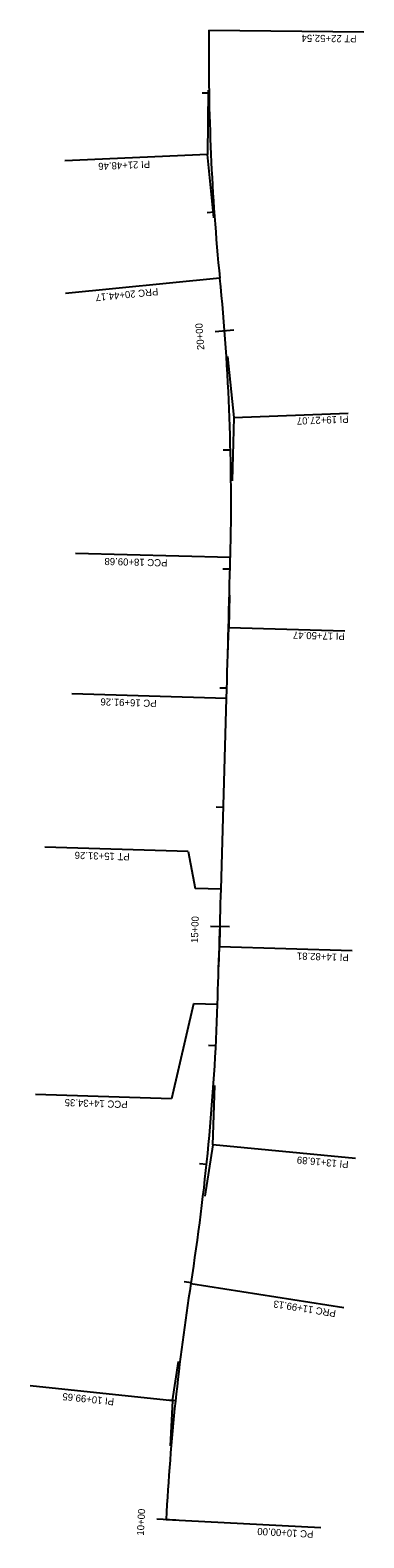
# Model space of a CAD drawing. Extents: x 1445613 to 1446340, y 2043492 to 2056486.
# Drawn here: x 1445971 to 1446251, y 2043492 to 2044757 of the extents above; entities that cross this region are included whole.
import ezdxf

# ---------------------------------------------------------------- set-up
doc = ezdxf.new("R2010")
doc.units = 0
for name, color, linetype in [('R_Horz Alg', 7, 'Continuous'), ('R_Horz Alg Annot', 7, 'Continuous'), ('R_Horz Alg Stationing', 7, 'Continuous')]:
    doc.layers.add(name, color=color, linetype=linetype)

msp = doc.modelspace()

# ---------------------------------------------------------------- linework, layer by layer
at = {"layer": 'R_Horz Alg'}
msp.add_line((1446131, 2044036.1), (1446135.6, 2044196.1), dxfattribs=at)
for centre, radius, start, end in [((1448030.5, 2044737.1), 1909.9, 179.4129, 185.664), ((1444229.5, 2044360.1), 1909.9, 358.629, 5.664), ((1423202.5, 2044863.3), 22942.8, 358.33333, 358.62905), ((1423197.9, 2044703.4), 22942.8, 358.09132, 358.33333), ((1444219.2, 2044002.9), 1909.9, 351.0345, 358.0913), ((1447992.2, 2043407.6), 1909.9, 171.0345, 177.0083)]:
    msp.add_arc(centre, radius, start, end, dxfattribs=at)
at = {"layer": 'R_Horz Alg Annot'}
for p, q in [((1446120.3, 2044706.3), (1446119.7, 2044652.4)), ((1446125, 2044599.2), (1446119.7, 2044652.4)), ((1446136.5, 2044482.8), (1446141.6, 2044431.8)), ((1446141.6, 2044431.8), (1446140.3, 2044378.7)), ((1446141.6, 2044431.8), (1446237.7, 2044435.4)), ((1446138, 2044282.6), (1446137.4, 2044255.2)), ((1446136.8, 2044234.2), (1446137.4, 2044255.2)), ((1446234.8, 2044252.6), (1446137.4, 2044255.2)), ((1446103.5, 2044067.7), (1446109.3, 2044036.7)), ((1446130, 2044003.5), (1446129.6, 2043987.7)), ((1446129, 2043970.8), (1446129.6, 2043987.7)), ((1446240.9, 2043984.2), (1446129.6, 2043987.7)), ((1446107.9, 2043939.9), (1446089.3, 2043860.1)), ((1446124, 2043821.6), (1446125.7, 2043871.3)), ((1446124, 2043821.6), (1446117.3, 2043778.6)), ((1446243.8, 2043810.2), (1446124, 2043821.6)), ((1446090.2, 2043606.8), (1446095.4, 2043639.7)), ((1446090.2, 2043606.8), (1446088.2, 2043569))]:
    msp.add_line(p, q, dxfattribs=at)
for points in [[(1446120.8, 2044756.7), (1446250.8, 2044755.3)], [(1446119.7, 2044652.4), (1445999.8, 2044647.1)], [(1446130, 2044548.6), (1446000.6, 2044535.8)], [(1446138.8, 2044314.4), (1446008.8, 2044317.5)], [(1446135.6, 2044196.1), (1446005.7, 2044199.8)], [(1446103.5, 2044067.7), (1445983.1, 2044071.2)], [(1446131, 2044036.1), (1446109.3, 2044036.7)], [(1446128, 2043939.3), (1446107.9, 2043939.9)], [(1446089.3, 2043860.1), (1445975.4, 2043863.9)], [(1446105.7, 2043705.2), (1446234.1, 2043685)], [(1446090.2, 2043606.8), (1445970.8, 2043619.3)], [(1446085, 2043507.3), (1446214.8, 2043500.5)]]:
    msp.add_lwpolyline(points, dxfattribs=at)
at = {"layer": 'R_Horz Alg Stationing'}
for points in [[(1446115, 2044704), (1446121, 2044704.1)], [(1446119.3, 2044603.8), (1446125.3, 2044604.2)], [(1446125.9, 2044504), (1446141.8, 2044505.2)], [(1446132.8, 2044404.6), (1446138.8, 2044404.7)], [(1446132.6, 2044304.9), (1446138.6, 2044304.7)], [(1446129.9, 2044205), (1446135.9, 2044204.8)], [(1446127, 2044105), (1446133, 2044104.8)], [(1446122.1, 2044005.1), (1446138.1, 2044004.6)], [(1446120.5, 2043905.2), (1446126.5, 2043904.9)], [(1446112.8, 2043805.9), (1446118.8, 2043805.2)], [(1446099.9, 2043707), (1446105.8, 2043706.1)], [(1446086.8, 2043607.6), (1446092.8, 2043607)], [(1446077, 2043507.7), (1446093, 2043506.9)]]:
    msp.add_lwpolyline(points, dxfattribs=at)

# ---------------------------------------------------------------- texts
at = {"layer": 'R_Horz Alg Annot'}
for s, rotation, p in [('PT 22+52.54', 179.4129, (1446244.7, 2044752.4)), ('PI 21+48.46', 182.5384, (1446071.3, 2044647.2)), ('PRC 20+44.17', 185.664, (1446078, 2044540.4)), ('PI 19+27.07', 182.1489, (1446237.9, 2044433.3)), ('PI 19+27.07', 182.1489, (1446237.9, 2044433.3)), ('PI 19+27.07', 182.1489, (1446237.9, 2044433.3)), ('PCC 18+09.68', 178.629, (1446086.1, 2044312.7)), ('PI 17+50.47', 178.4866, (1446234.9, 2044251)), ('PC 16+91.26', 178.3333, (1446077, 2044194.8)), ('PT 15+31.26', 178.3333, (1446054.4, 2044066.1)), ('PI 14+82.81', 178.2032, (1446238.2, 2043981.6)), ('PCC 14+34.35', 178.0913, (1446052.7, 2043858.3)), ('PI 13+16.89', 174.728, (1446238.2, 2043807.9)), ('PRC 11+99.13', 171.0345, (1446227.7, 2043682.9)), ('PI 10+99.65', 174.0214, (1446041.5, 2043608.9)), ('PC 10+00.00', 177.0083, (1446208.6, 2043497.8))]:
    msp.add_text(s, height=6, rotation=rotation, dxfattribs=at).set_placement(p)
at = {"layer": 'R_Horz Alg Stationing'}
for s, rotation, p in [('20+00', 94.3388, (1446117, 2044488.6)), ('15+00', 88.2553, (1446111.6, 2043990.8)), ('10+00', 87.0083, (1446066.2, 2043493.6))]:
    msp.add_text(s, height=6, rotation=rotation, dxfattribs=at).set_placement(p)

doc.saveas('drawing.dxf')
